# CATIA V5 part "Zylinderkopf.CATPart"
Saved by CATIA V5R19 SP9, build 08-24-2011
Part number: Zylinderkopf
Bounding box of the stored display mesh (mm): x -100 to 100, y -75 to 75, z 0 to 100
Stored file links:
  C:\Documents and Settings\olmethn\Desktop\Zylinderkopf.CATPart
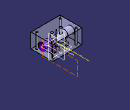
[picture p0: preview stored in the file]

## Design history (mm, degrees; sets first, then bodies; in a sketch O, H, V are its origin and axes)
TTRSSet1
f4a2d38f3ddc11d3a929006094b99c4b_11 "CATTPSSet"
Body1 (main body)
  Sketch1 on xy-plane, origin (0, 0, 0), H (1, 0, 0), V (0, 1, 0)
    line L1 (100, 75) -> (100, -75)
    line L2 (100, -75) -> (-100, -75)
    line L3 (-100, -75) -> (-100, 75)
    line L4 (-100, 75) -> (100, 75)
    length L4 = 200
    length L1 = 150
    vertical: L1 V, L3 V
    horizontal: L2 H, L4 H
    equidistance: L1 L3 O, L2 L4 O
  Pad1: profile Sketch1, direction (0, 0, 1), length 100
  Sketch2 on end face of Pad1, origin (0, 0, 100), H (1, 0, 0), V (0, 1, 0)
    circle A1 centre (80, -55) radius 6.25
    point P1 (80, -55)
    reference intersected line E1 (100, 75) -> (100, -75) from face of Pad1 from Sketch1.L1
    reference intersected line E2 (100, -75) -> (-100, -75) from face of Pad1 from Sketch1.L2
    reference intersected line E3 through (0, 0) direction (-1, 0) from zx-plane
    circle A2 centre (80, 55) radius 6.25
    reference intersected line E4 through (0, 0) direction (0, 1) from yz-plane
    circle A3 centre (-80, -55) radius 6.25
    circle A4 centre (-80, 55) radius 6.25
    distance P1 E1 = 20
    distance P1 E2 = 20
    radius A1 = 6.25
    symmetry: A1 A2 E3, A1 A3 E4, A2 A4 E4
  Pocket1: profile Sketch2, direction (0, 0, -1), through (limit type 3)
  Sketch3 on face of Pad1 from Sketch1.L3, origin (-100, 0, 0), H (0, 1, 0), V (0, 0, 1)
    circle A1 centre (0, 50) radius 25
    point P1 (0, 50)
    reference intersected line E1 (75, 0) -> (-75, 0) from start face of Pad1
    reference intersected line E2 (-75, 100) -> (75, 100) from end face of Pad1
    reference intersected line E3 (75, 0) -> (-75, 0) from start face of Pad1
    distance E1 E2 = 100 (reference)
    distance P1 E3 = 50
    radius A1 = 25
    coincidence: P1 V
  Sketch4 on zx-plane, origin (0, 0, 0), H (-1, 0, 0), V (0, 0, 1)
    line L1 (113.2441, 50) -> (55, 50)
    arc A1 centre (55, 25) radius 25 from (55, 50) to (30, 25) ccw
    line L2 (30, 25) -> (30, -31.3359)
    reference intersected line E1 (100, 0) -> (-100, 0) from start face of Pad1
    reference intersected line E2 through (0, 0) direction (0, -1) from yz-plane
    distance L1 E1 = 50
    distance E2 L2 = 30
    radius A1 = 25
    horizontal: L1 H
    tangency: A1 L1, L2 A1
  Slot1: profile Sketch3, centre curve Sketch4
  Mirror1: of Slot1, Sketch3, Sketch4, about yz-plane
  Sketch5 on start face of Pad1, origin (0, 0, 0), H (1, 0, 0), V (0, -1, 0)
    circle A1 centre (30, 0) radius 8
    point P1 (30, 0)
    reference projected circle E1 centre (30, 0) radius 25 from edge [face of Mirror1 | start face of Pad1]
    reference intersected line E2 through (0, 0) direction (0, 1) from yz-plane
    circle A2 centre (-30, 0) radius 8
    circle A3 centre (0, 0) radius 3
    radius A1 = 8
    radius A3 = 3
    coincidence: P1 H
    concentricity: P1 E1
    symmetry: A1 A2 E2
  Pocket2: profile Sketch5, direction (0, 0, 1), through (limit type 3)
  Sketch6 on zx-plane, origin (0, 0, 0), H (-1, 0, 0), V (0, 0, 1)
    circle A1 centre (65, 5) radius 2.5
    point P1 (65, 5)
    reference intersected line E1 (100, 0) -> (-100, 0) from start face of Pad1
    reference intersected line E2 through (0, 0) direction (0, -1) from yz-plane
    radius A1 = 2.5
    distance P1 E1 = 5
    distance E2 P1 = 65
  Sketch7 on start face of Pad1, origin (0, 0, 0), H (1, 0, 0), V (0, -1, 0)
    construction line L1 (-30, 0) -> (30, 0)
    point P1 (-30, 0)
    point P2 (30, 0)
    arc A1 centre (30, 0) radius 32.5 from (7.0588, 23.0207) to (7.0588, -23.0207) cw
    arc A2 centre (-30, 0) radius 32.5 from (-7.0588, -23.0207) to (-7.0588, 23.0207) cw
    reference projected circle E1 centre (30, 0) radius 25 from edge [face of Mirror1 | start face of Pad1]
    reference projected circle E2 centre (-30, 0) radius 25 from edge [face of Slot1 | start face of Pad1]
    arc A3 centre (0, -30.104) radius 10 from (-7.0588, -23.0207) to (7.0588, -23.0207) cw
    arc A4 centre (0, 30.104) radius 10 from (-7.0588, 23.0207) to (7.0588, 23.0207) ccw
    radius A3 = 10
    radius A4 = 10
    radius A1 = 32.5
    radius A2 = 32.5
    coincidence: P1 H
    horizontal: L1 H
    concentricity: P2 E1, P1 E2
    tangency: A3 A2, A3 A1, A4 A2, A4 A1
  Slot2: profile Sketch6, centre curve Sketch7
  Sketch8 on start face of Pad1, origin (0, 0, 0), H (1, 0, 0), V (0, -1, 0)
    construction line L1 (57.997, -21.4589) -> (48.4236, -29.8505)
    line L2 (59.6449, -23.3389) -> (50.0715, -31.7305)
    line L3 (46.7756, -27.9705) -> (56.3491, -19.5789)
    arc A1 centre (48.4236, -29.8505) radius 2.5 from (50.0715, -31.7305) to (46.7756, -27.9705) cw
    arc A2 centre (57.997, -21.4589) radius 2.5 from (56.3491, -19.5789) to (59.6449, -23.3389) cw
    point P3 (59.6449, -23.3389)
    point P4 (50.0715, -31.7305)
    point P5 (46.7756, -27.9705)
    point P6 (56.3491, -19.5789)
    reference intersected line E1 through (0, 0) direction (1, 0) from zx-plane
    construction line L4 (57.997, 21.4589) -> (48.4236, 29.8505)
    point P11 (59.6449, 23.3389)
    point P12 (50.0715, 31.7305)
    point P13 (46.7756, 27.9705)
    point P14 (56.3491, 19.5789)
    line L5 (59.6449, 23.3389) -> (50.0715, 31.7305)
    line L6 (46.7756, 27.9705) -> (56.3491, 19.5789)
    arc A3 centre (48.4236, 29.8505) radius 2.5 from (50.0715, 31.7305) to (46.7756, 27.9705) ccw
    arc A4 centre (57.997, 21.4589) radius 2.5 from (56.3491, 19.5789) to (59.6449, 23.3389) ccw
    reference intersected line E2 through (0, 0) direction (0, 1) from yz-plane
    construction line L7 (-57.997, -21.4589) -> (-48.4236, -29.8505)
    point P19 (-59.6449, -23.3389)
    point P20 (-50.0715, -31.7305)
    point P21 (-46.7756, -27.9705)
    point P22 (-56.3491, -19.5789)
    construction line L8 (-57.997, 21.4589) -> (-48.4236, 29.8505)
    point P25 (-59.6449, 23.3389)
    point P26 (-50.0715, 31.7305)
    point P27 (-46.7756, 27.9705)
    point P28 (-56.3491, 19.5789)
    line L9 (-59.6449, -23.3389) -> (-50.0715, -31.7305)
    line L10 (-46.7756, -27.9705) -> (-56.3491, -19.5789)
    arc A5 centre (-48.4236, -29.8505) radius 2.5 from (-50.0715, -31.7305) to (-46.7756, -27.9705) ccw
    arc A6 centre (-57.997, -21.4589) radius 2.5 from (-56.3491, -19.5789) to (-59.6449, -23.3389) ccw
    line L11 (-59.6449, 23.3389) -> (-50.0715, 31.7305)
    line L12 (-46.7756, 27.9705) -> (-56.3491, 19.5789)
    arc A7 centre (-48.4236, 29.8505) radius 2.5 from (-50.0715, 31.7305) to (-46.7756, 27.9705) cw
    arc A8 centre (-57.997, 21.4589) radius 2.5 from (-56.3491, 19.5789) to (-59.6449, 23.3389) cw
    distance L1 L2 = 2.5
    tangency: A1 L2, A2 L2, A1 L3, A2 L3
    symmetry: L1 L4 E1, P3 P11 E1, P4 P12 E1, P5 P13 E1, P6 P14 E1, L2 L5 E1, L3 L6 E1, A1 A3 E1, A2 A4 E1, L1 L7 E2, P3 P19 E2, P4 P20 E2, P5 P21 E2, P6 P22 E2, L4 L8 E2, P11 P25 E2, P12 P26 E2, P13 P27 E2, P14 P28 E2, L2 L9 E2, L3 L10 E2, A1 A5 E2, A2 A6 E2, L5 L11 E2, L6 L12 E2, A3 A7 E2, A4 A8 E2
  Pocket3: profile Sketch8, direction (0, 0, 1), length 5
